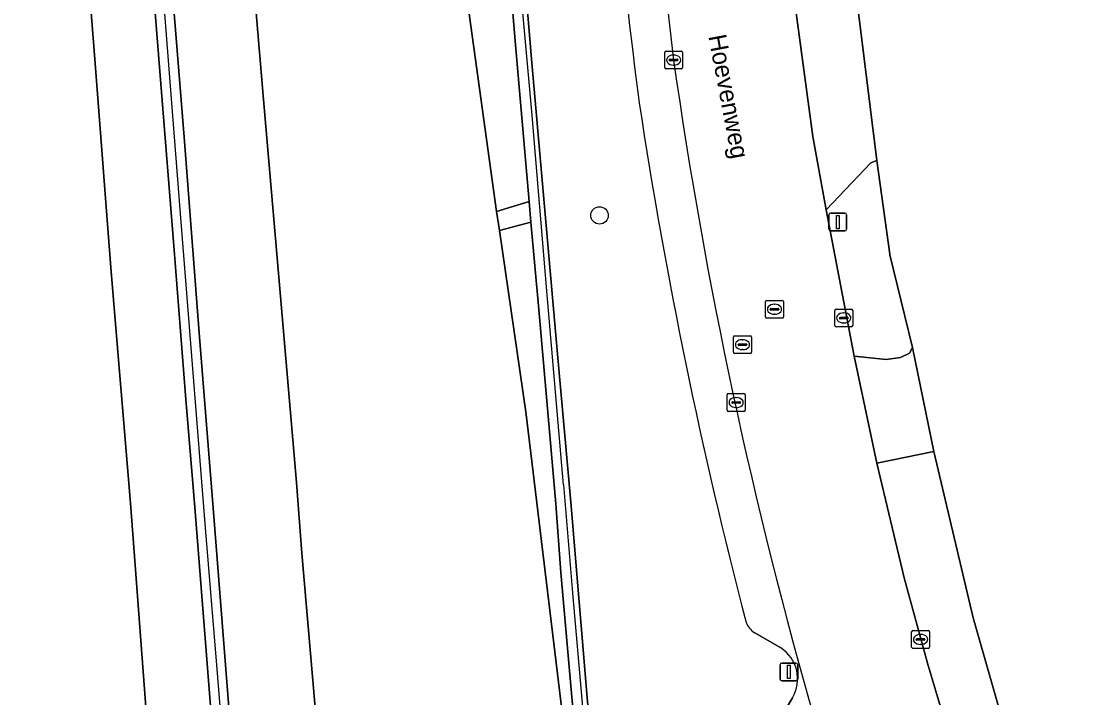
# Model space of a CAD drawing. Extents: x 157692 to 159674, y 381452 to 383291.
# Drawn here: x 157863.7 to 157922.9, y 381629.2 to 381667.1 of the extents above; entities that cross this region are included whole.
import ezdxf

# ---------------------------------------------------------------- set-up
doc = ezdxf.new("R2010")
doc.units = 0
for name, color, linetype in [('IMGEO_Berm_groen', 7, 'Continuous'), ('IMGEO_Boom', 7, 'Continuous'), ('IMGEO_Erf', 7, 'Continuous'), ('IMGEO_Geluidsscherm', 7, 'Continuous'), ('IMGEO_Groenvoorziening', 7, 'Continuous'), ('IMGEO_Kolk', 7, 'Continuous'), ('IMGEO_Lichtmast', 7, 'Continuous'), ('IMGEO_Muur', 7, 'Continuous'), ('IMGEO_Openbare_ruimte_label', 7, 'Continuous'), ('IMGEO_Parkeervlak_open', 7, 'Continuous'), ('IMGEO_Rijbaan_autosnelweg', 7, 'Continuous'), ('IMGEO_Rijbaan_autoweg', 7, 'Continuous'), ('IMGEO_Rijbaan_lokaal_gesloten', 7, 'Continuous'), ('IMGEO_Rioolput', 7, 'Continuous'), ('IMGEO_Voetpad_open', 7, 'Continuous')]:
    doc.layers.add(name, color=color, linetype=linetype)

msp = doc.modelspace()

# ---------------------------------------------------------------- linework, layer by layer
at = {"layer": 'IMGEO_Berm_groen'}
for points in [[(157867.965, 381722.303), (157868.994, 381709.276), (157869.88, 381698.16), (157870.87, 381685.864), (157871.828, 381673.372), (157872.842, 381660.625), (157873.712, 381649.4), (157874.498, 381639.59), (157875.594, 381625.546), (157876.484, 381614.198), (157877.279, 381604.704), (157878.126, 381593.661)], [(157877.434, 381589.695), (157876.669, 381599.29), (157875.872, 381609.289), (157874.963, 381620.654), (157874.164, 381630.852), (157873.473, 381639.621), (157872.935, 381646.148), (157872.278, 381654.539), (157871.543, 381663.616), (157870.896, 381671.836), (157870.352, 381678.919), (157869.739, 381686.472), (157869.25, 381692.912), (157868.64, 381700.422), (157867.915, 381709.715), (157867.171, 381719.374)], [(157863.732, 381717.086), (157864.635, 381706.057), (157865.474, 381695.412), (157866.333, 381684.381), (157867.087, 381674.55), (157867.859, 381664.764), (157868.754, 381653.066), (157869.845, 381640.086), (157870.805, 381627.181), (157871.895, 381613.885), (157872.944, 381600.363), (157873.76, 381590.175)], [(157884.249, 381713.789), (157885.718, 381694.582), (157886.683, 381684.924), (157887.404, 381678.445), (157888.701, 381668.639), (157890.369, 381656.458), (157892.204, 381657.014), (157892.013, 381659.154), (157891.404, 381666.233), (157890.517, 381676.962), (157889.471, 381689.083), (157888.65, 381698.565), (157887.932, 381707.729), (157887.155, 381717.191)], [(157883.242, 381593.296), (157882.445, 381602.817), (157881.422, 381614.915), (157880.419, 381626.031), (157879.461, 381637.285), (157879.148, 381641.247), (157878.255, 381651.695), (157877.308, 381662.744), (157876.45, 381672.935), (157875.49, 381684.241), (157874.611, 381694.819), (157873.682, 381705.524), (157873, 381713.591)]]:
    msp.add_lwpolyline(points, dxfattribs=at)
for points in [[(157890.369, 381656.458), (157890.552, 381655.387), (157892.308, 381655.853), (157892.204, 381657.014)], [(157896.492, 381572.256), (157899.256, 381574.148), (157898.47, 381584.121), (157897.751, 381592.572), (157897.07, 381600.846), (157896.254, 381610.059), (157895.493, 381618.788), (157894.791, 381627.105), (157893.991, 381636.202), (157893.71, 381640.067), (157892.745, 381650.96), (157892.308, 381655.853), (157890.552, 381655.387), (157892.024, 381645.22), (157894.258, 381626.649), (157895.097, 381617.5), (157896.096, 381606.158), (157896.433, 381601.439), (157896.643, 381597.697), (157896.668, 381594.368), (157896.501, 381586.539), (157896.379, 381579.545), (157896.402, 381576.024)]]:
    msp.add_lwpolyline(points, close=True, dxfattribs=at)
at = {"layer": 'IMGEO_Boom'}
msp.add_circle((157896.156, 381656.236), 0.489, dxfattribs=at)
at = {"layer": 'IMGEO_Erf'}
msp.add_lwpolyline([(157906.185, 381715.359), (157906.632, 381710.048), (157906.823, 381707.782), (157907.103, 381704.46), (157908.594, 381685.1), (157909.227, 381677.958), (157910.66, 381667.904), (157911.715, 381659.318), (157912.44, 381654.067), (157912.445, 381654.034), (157913.71, 381648.82), (157914.922, 381642.995), (157917.13, 381633.664), (157918.988, 381627.119), (157922.624, 381615.817), (157924.2, 381611.589)], dxfattribs=at)
at = {"layer": 'IMGEO_Geluidsscherm'}
for points in [[(157874.053, 381638.712), (157872.666, 381656.094), (157871.737, 381668.027), (157870.721, 381681.637), (157869.567, 381696.23), (157868.32, 381712.586), (157867.159, 381726.489), (157865.954, 381741.209), (157864.809, 381756.45), (157863.806, 381768.982), (157862.385, 381786.19), (157861.408, 381800.707), (157860.147, 381816.502), (157858.882, 381832.382), (157857.547, 381849.595), (157856.042, 381866.756), (157854.906, 381881.824), (157854.737, 381883.41), (157854.585, 381886.29)], [(157894.139, 381641.124), (157893.247, 381651.551), (157892.35, 381662.063), (157891.41, 381672.573), (157890.762, 381680.814), (157889.905, 381691.372), (157889.058, 381701.758), (157888.118, 381712.268), (157887.113, 381724.843), (157885.957, 381739.479), (157885.015, 381750.851), (157883.817, 381765.443), (157882.659, 381780.122), (157881.699, 381792.657), (157880.689, 381805.318), (157879.686, 381817.851), (157878.57, 381832.532), (157877.418, 381847.083), (157876.408, 381859.744), (157875.211, 381874.335), (157874.447, 381884.768)], [(157894.139, 381641.124), (157894.664, 381634.836), (157895.393, 381626.521), (157896.097, 381618.176), (157896.848, 381609.781), (157897.555, 381601.383), (157898.468, 381590.92), (157899.133, 381582.619)], [(157879.494, 381570.792), (157878.734, 381579.503), (157878.173, 381587.558), (157877.584, 381594.816), (157876.915, 381603.515), (157876.23, 381611.851), (157875.519, 381620.655), (157874.697, 381630.788), (157874.053, 381638.712)]]:
    msp.add_lwpolyline(points, dxfattribs=at)
at = {"layer": 'IMGEO_Groenvoorziening'}
for points in [[(157888.108, 381715.453), (157889.505, 381698.696), (157890.183, 381690.305), (157891.621, 381673.593), (157892.319, 381665.225), (157893.803, 381648.451), (157894.543, 381640.157), (157895.955, 381623.379), (157896.687, 381615.009), (157897.409, 381606.657), (157898.127, 381598.223)], [(157906.332, 381631.979), (157904.866, 381632.821)], [(157906.226, 381627.907), (157906.98, 381629.172)]]:
    msp.add_lwpolyline(points, dxfattribs=at)
for centre, radius, start, end in [((158259.967, 381709.911), 364.671, 183.80761, 187.46156), ((158179.201, 381705.152), 284.03, 188.62544, 194.63107), ((157905.554, 381633.882), 1.264, 201.99885, 237.01446), ((157905.189, 381630.237), 2.084, 329.27551, 56.72266)]:
    msp.add_arc(centre, radius, start, end, dxfattribs=at)
at = {"layer": 'IMGEO_Kolk'}
for p, q in [((157899.813, 381664.525), (157899.813, 381665.377)), ((157899.888, 381665.451), (157900.74, 381665.451)), ((157900.072, 381664.945), (157900.072, 381664.957)), ((157900.115, 381664.994), (157900.513, 381664.994)), ((157900.301, 381665.231), (157900.326, 381665.231)), ((157900.556, 381664.957), (157900.556, 381664.945)), ((157900.814, 381665.377), (157900.814, 381664.525)), ((157900.74, 381664.451), (157899.888, 381664.451)), ((157900.51, 381664.908), (157900.112, 381664.908)), ((157900.324, 381664.671), (157900.299, 381664.671)), ((157909.36, 381650.059), (157909.36, 381650.911)), ((157909.435, 381650.985), (157910.287, 381650.985)), ((157909.848, 381650.765), (157909.873, 381650.765)), ((157910.361, 381650.911), (157910.361, 381650.059)), ((157909.619, 381650.479), (157909.619, 381650.491)), ((157910.057, 381650.442), (157909.659, 381650.442)), ((157909.662, 381650.528), (157910.06, 381650.528)), ((157909.871, 381650.205), (157909.846, 381650.205)), ((157910.103, 381650.491), (157910.103, 381650.479)), ((157910.287, 381649.985), (157909.435, 381649.985)), ((157903.323, 381645.315), (157903.323, 381646.167)), ((157903.398, 381646.241), (157904.25, 381646.241)), ((157903.811, 381646.021), (157903.836, 381646.021)), ((157904.324, 381646.167), (157904.324, 381645.315)), ((157903.582, 381645.735), (157903.582, 381645.747)), ((157904.02, 381645.698), (157903.622, 381645.698)), ((157903.625, 381645.784), (157904.023, 381645.784)), ((157903.834, 381645.461), (157903.809, 381645.461)), ((157904.066, 381645.747), (157904.066, 381645.735)), ((157904.25, 381645.241), (157903.398, 381645.241)), ((157913.67, 381632.026), (157913.67, 381632.878)), ((157913.745, 381632.952), (157914.597, 381632.952)), ((157913.929, 381632.446), (157913.929, 381632.458)), ((157914.367, 381632.409), (157913.969, 381632.409)), ((157913.972, 381632.495), (157914.37, 381632.495)), ((157914.158, 381632.732), (157914.183, 381632.732)), ((157914.413, 381632.458), (157914.413, 381632.446)), ((157914.671, 381632.878), (157914.671, 381632.026)), ((157914.597, 381631.952), (157913.745, 381631.952)), ((157914.181, 381632.172), (157914.156, 381632.172))]:
    msp.add_line(p, q, dxfattribs=at)
for points in [[(157899.813, 381664.525), (157899.813, 381665.377)], [(157899.888, 381665.451), (157900.74, 381665.451)], [(157900.814, 381665.377), (157900.814, 381664.525)], [(157900.74, 381664.451), (157899.888, 381664.451)], [(157909.36, 381650.059), (157909.36, 381650.911)], [(157909.435, 381650.985), (157910.287, 381650.985)], [(157910.361, 381650.911), (157910.361, 381650.059)], [(157910.287, 381649.985), (157909.435, 381649.985)], [(157903.323, 381645.315), (157903.323, 381646.167)], [(157903.398, 381646.241), (157904.25, 381646.241)], [(157904.324, 381646.167), (157904.324, 381645.315)], [(157904.25, 381645.241), (157903.398, 381645.241)], [(157913.67, 381632.026), (157913.67, 381632.878)], [(157913.745, 381632.952), (157914.597, 381632.952)], [(157914.671, 381632.878), (157914.671, 381632.026)], [(157914.597, 381631.952), (157913.745, 381631.952)]]:
    msp.add_lwpolyline(points, dxfattribs=at)
for centre, radius, start, end in [((157899.89, 381665.375), 0.0765, 91.55205, 178.44795), ((157899.89, 381665.375), 0.0765, 91.55205, 178.44795), ((157900.112, 381664.954), 0.0403, 85.87752, 175.75265), ((157900.109, 381664.944), 0.0366, 178.93798, 274.71019), ((157900.513, 381664.951), 0.043, 264.86636, 352.45326), ((157900.517, 381664.956), 0.0386, 1.73085, 96.63898), ((157900.738, 381665.375), 0.0765, 1.55205, 88.44795), ((157900.738, 381665.375), 0.0765, 1.55205, 88.44795), ((157899.89, 381664.527), 0.0765, 181.55205, 268.44795), ((157899.89, 381664.527), 0.0765, 181.55205, 268.44795), ((157900.738, 381664.527), 0.0765, 271.55205, 358.44795), ((157900.738, 381664.527), 0.0765, 271.55205, 358.44795), ((157909.437, 381650.909), 0.0765, 91.55205, 178.44795), ((157909.437, 381650.909), 0.0765, 91.55205, 178.44795), ((157910.285, 381650.909), 0.0765, 1.55205, 88.44795), ((157910.285, 381650.909), 0.0765, 1.55205, 88.44795), ((157909.659, 381650.488), 0.0403, 85.87752, 175.75265), ((157909.656, 381650.478), 0.0366, 178.93798, 274.71019), ((157910.06, 381650.485), 0.043, 264.86636, 352.45326), ((157910.064, 381650.49), 0.0386, 1.73085, 96.63898), ((157909.437, 381650.061), 0.0765, 181.55205, 268.44795), ((157909.437, 381650.061), 0.0765, 181.55205, 268.44795), ((157910.285, 381650.061), 0.0765, 271.55205, 358.44795), ((157910.285, 381650.061), 0.0765, 271.55205, 358.44795), ((157903.4, 381646.165), 0.0765, 91.55205, 178.44795), ((157903.4, 381646.165), 0.0765, 91.55205, 178.44795), ((157904.248, 381646.165), 0.0765, 1.55205, 88.44795), ((157904.248, 381646.165), 0.0765, 1.55205, 88.44795), ((157903.622, 381645.744), 0.0403, 85.87752, 175.75265), ((157903.619, 381645.734), 0.0366, 178.93798, 274.71019), ((157904.023, 381645.741), 0.043, 264.86636, 352.45326), ((157904.027, 381645.746), 0.0386, 1.73085, 96.63898), ((157903.4, 381645.317), 0.0765, 181.55205, 268.44795), ((157903.4, 381645.317), 0.0765, 181.55205, 268.44795), ((157904.248, 381645.317), 0.0765, 271.55205, 358.44795), ((157904.248, 381645.317), 0.0765, 271.55205, 358.44795), ((157913.747, 381632.876), 0.0765, 91.55205, 178.44795), ((157913.747, 381632.876), 0.0765, 91.55205, 178.44795), ((157913.969, 381632.455), 0.0403, 85.87752, 175.75265), ((157913.966, 381632.445), 0.0366, 178.93798, 274.71019), ((157914.37, 381632.452), 0.043, 264.86636, 352.45326), ((157914.374, 381632.457), 0.0386, 1.73085, 96.63898), ((157914.595, 381632.876), 0.0765, 1.55205, 88.44795), ((157914.595, 381632.876), 0.0765, 1.55205, 88.44795), ((157913.747, 381632.028), 0.0765, 181.55205, 268.44795), ((157913.747, 381632.028), 0.0765, 181.55205, 268.44795), ((157914.595, 381632.028), 0.0765, 271.55205, 358.44795), ((157914.595, 381632.028), 0.0765, 271.55205, 358.44795)]:
    msp.add_arc(centre, radius, start, end, dxfattribs=at)
for centre, major_axis, ratio, start_param, end_param in [((157900.3, 381664.951), (-0.387, 0.002), 0.722429, 4.712389, 7.853982), ((157900.325, 381664.951), (-0.39, 0.002), 0.717154, 1.570796, 4.712389), ((157909.847, 381650.485), (-0.387, 0.002), 0.722429, 4.712389, 7.853982), ((157909.872, 381650.485), (-0.39, 0.002), 0.717154, 1.570796, 4.712389), ((157903.81, 381645.741), (-0.387, 0.002), 0.722429, 4.712389, 7.853982), ((157903.835, 381645.741), (-0.39, 0.002), 0.717154, 1.570796, 4.712389), ((157914.157, 381632.452), (-0.387, 0.002), 0.722429, 4.712389, 7.853982), ((157914.182, 381632.452), (-0.39, 0.002), 0.717154, 1.570796, 4.712389)]:
    msp.add_ellipse(centre, major_axis=major_axis, ratio=ratio, start_param=start_param, end_param=end_param, dxfattribs=at)
at = {"layer": 'IMGEO_Lichtmast'}
for p, q in [((157909.027, 381655.465), (157909.027, 381656.265)), ((157909.027, 381656.265), (157909.027, 381655.465)), ((157909.127, 381656.365), (157909.917, 381656.365)), ((157909.917, 381656.365), (157909.127, 381656.365)), ((157910.017, 381656.265), (157910.017, 381655.465)), ((157910.017, 381655.465), (157910.017, 381656.265)), ((157909.917, 381655.365), (157909.127, 381655.365)), ((157909.127, 381655.365), (157909.917, 381655.365)), ((157906.291, 381630.229), (157906.291, 381631.029)), ((157906.291, 381631.029), (157906.291, 381630.229)), ((157906.391, 381631.129), (157907.181, 381631.129)), ((157907.181, 381631.129), (157906.391, 381631.129)), ((157907.281, 381631.029), (157907.281, 381630.229)), ((157907.281, 381630.229), (157907.281, 381631.029)), ((157907.181, 381630.129), (157906.391, 381630.129)), ((157906.391, 381630.129), (157907.181, 381630.129))]:
    msp.add_line(p, q, dxfattribs=at)
for points in [[(157909.447, 381656.24), (157909.597, 381656.24), (157909.597, 381655.49), (157909.447, 381655.49), (157909.447, 381656.24)], [(157906.711, 381631.004), (157906.861, 381631.004), (157906.861, 381630.254), (157906.711, 381630.254), (157906.711, 381631.004)]]:
    msp.add_lwpolyline(points, dxfattribs=at)
for centre, start, end in [((157909.127, 381656.265), 90, 180), ((157909.127, 381656.265), 90, 180), ((157909.917, 381656.265), 0, 90), ((157909.917, 381656.265), 360, 90), ((157909.127, 381655.465), 180, 270), ((157909.127, 381655.465), 180, 270), ((157909.917, 381655.465), 270, 0), ((157909.917, 381655.465), 270, 0), ((157906.391, 381631.029), 90, 180), ((157906.391, 381631.029), 90, 180), ((157907.181, 381631.029), 0, 90), ((157907.181, 381631.029), 360, 90), ((157906.391, 381630.229), 180, 270), ((157906.391, 381630.229), 180, 270), ((157907.181, 381630.229), 270, 0), ((157907.181, 381630.229), 270, 0)]:
    msp.add_arc(centre, 0.1, start, end, dxfattribs=at)
at = {"layer": 'IMGEO_Muur'}
for points in [[(157878.126, 381593.661), (157877.279, 381604.704), (157876.484, 381614.198), (157875.594, 381625.546), (157874.498, 381639.59), (157873.712, 381649.4), (157872.842, 381660.625), (157871.828, 381673.372), (157870.87, 381685.864), (157869.88, 381698.16), (157868.994, 381709.276), (157867.965, 381722.303)], [(157867.171, 381719.374), (157867.915, 381709.715), (157868.64, 381700.422), (157869.25, 381692.912), (157869.739, 381686.472), (157870.352, 381678.919), (157870.896, 381671.836), (157871.543, 381663.616), (157872.278, 381654.539), (157872.935, 381646.148), (157873.473, 381639.621), (157874.164, 381630.852), (157874.963, 381620.654), (157875.872, 381609.289), (157876.669, 381599.29), (157877.434, 381589.695)], [(157887.155, 381717.191), (157887.932, 381707.729), (157888.65, 381698.565), (157889.471, 381689.083), (157890.517, 381676.962), (157891.404, 381666.233), (157892.013, 381659.154), (157892.204, 381657.014), (157892.308, 381655.853), (157892.745, 381650.96), (157893.71, 381640.067), (157893.991, 381636.202), (157894.791, 381627.105), (157895.493, 381618.788), (157896.254, 381610.059), (157897.07, 381600.846), (157897.751, 381592.572)], [(157898.127, 381598.223), (157897.409, 381606.657), (157896.687, 381615.009), (157895.955, 381623.379), (157894.543, 381640.157), (157893.803, 381648.451), (157892.319, 381665.225), (157891.621, 381673.593), (157890.183, 381690.305), (157889.505, 381698.696), (157888.108, 381715.453)]]:
    msp.add_lwpolyline(points, dxfattribs=at)
at = {"layer": 'IMGEO_Parkeervlak_open'}
for points in [[(157904.866, 381632.821), (157906.332, 381631.979)], [(157906.98, 381629.172), (157906.226, 381627.907)]]:
    msp.add_lwpolyline(points, dxfattribs=at)
for centre, radius, start, end in [((158259.967, 381709.911), 364.671, 183.80761, 187.46156), ((158256.833, 381709.082), 359.24, 183.68815, 187.05643), ((158168.422, 381702.972), 270.79, 188.07141, 196.11515), ((158179.201, 381705.152), 284.03, 188.62544, 194.63107), ((157905.554, 381633.882), 1.264, 201.99885, 237.01446), ((157905.189, 381630.237), 2.084, 329.27551, 56.72266)]:
    msp.add_arc(centre, radius, start, end, dxfattribs=at)
at = {"layer": 'IMGEO_Rijbaan_autosnelweg'}
msp.add_lwpolyline([(157873.76, 381590.175), (157872.944, 381600.363), (157871.895, 381613.885), (157870.805, 381627.181), (157869.845, 381640.086), (157868.754, 381653.066), (157867.859, 381664.764), (157867.087, 381674.55), (157866.333, 381684.381), (157865.474, 381695.412), (157864.635, 381706.057), (157863.732, 381717.086)], dxfattribs=at)
at = {"layer": 'IMGEO_Rijbaan_autoweg'}
for points in [[(157873, 381713.591), (157873.682, 381705.524), (157874.611, 381694.819), (157875.49, 381684.241), (157876.45, 381672.935), (157877.308, 381662.744), (157878.255, 381651.695), (157879.148, 381641.247), (157879.461, 381637.285), (157880.419, 381626.031), (157881.422, 381614.915), (157882.445, 381602.817), (157883.242, 381593.296)], [(157896.643, 381597.697), (157896.433, 381601.439), (157896.096, 381606.158), (157895.097, 381617.5), (157894.258, 381626.649), (157892.024, 381645.22), (157890.552, 381655.387), (157890.369, 381656.458), (157888.701, 381668.639), (157887.404, 381678.445), (157886.683, 381684.924), (157885.718, 381694.582), (157884.249, 381713.789)]]:
    msp.add_lwpolyline(points, dxfattribs=at)
at = {"layer": 'IMGEO_Rijbaan_lokaal_gesloten'}
for points in [[(157913.243, 381635.916), (157911.724, 381642.343), (157910.44, 381648.348), (157908.881, 381656.557), (157908.129, 381660.655), (157906.903, 381669.7), (157906.153, 381677.146), (157905.381, 381686.421), (157898.337, 381685.974)], [(158001.519, 381596.351), (158001.415, 381596.346), (157943.247, 381593.747), (157941.787, 381593.953), (157940.201, 381594.263), (157937.982, 381594.948), (157935.779, 381595.742), (157933.913, 381596.673), (157931.88, 381597.897), (157929.284, 381599.727), (157927.609, 381601.111), (157925.926, 381602.819), (157924.801, 381604.213), (157923.565, 381606.033), (157922.451, 381608.183), (157920.957, 381611.715), (157919.038, 381616.874), (157916.313, 381625.205), (157914.556, 381631.129), (157913.243, 381635.916)]]:
    msp.add_lwpolyline(points, dxfattribs=at)
for centre, radius, start, end in [((158256.833, 381709.082), 359.24, 183.68815, 187.05643), ((158168.422, 381702.972), 270.79, 188.07141, 196.11515)]:
    msp.add_arc(centre, radius, start, end, dxfattribs=at)
at = {"layer": 'IMGEO_Rioolput'}
for p, q in [((157905.475, 381650.546), (157905.475, 381651.398)), ((157905.55, 381651.472), (157906.402, 381651.472)), ((157906.476, 381651.398), (157906.476, 381650.546)), ((157905.734, 381650.966), (157905.734, 381650.978)), ((157906.172, 381650.929), (157905.774, 381650.929)), ((157905.777, 381651.015), (157906.175, 381651.015)), ((157905.963, 381651.252), (157905.988, 381651.252)), ((157906.218, 381650.978), (157906.218, 381650.966)), ((157906.402, 381650.472), (157905.55, 381650.472)), ((157905.986, 381650.692), (157905.961, 381650.692)), ((157903.679, 381648.56), (157903.679, 381649.412)), ((157903.754, 381649.486), (157904.606, 381649.486)), ((157903.938, 381648.98), (157903.938, 381648.992)), ((157904.376, 381648.943), (157903.978, 381648.943)), ((157903.981, 381649.029), (157904.379, 381649.029)), ((157904.167, 381649.266), (157904.192, 381649.266)), ((157904.422, 381648.992), (157904.422, 381648.98)), ((157904.68, 381649.412), (157904.68, 381648.56)), ((157904.606, 381648.486), (157903.754, 381648.486)), ((157904.19, 381648.706), (157904.165, 381648.706))]:
    msp.add_line(p, q, dxfattribs=at)
for points in [[(157905.475, 381650.546), (157905.475, 381651.398)], [(157905.55, 381651.472), (157906.402, 381651.472)], [(157906.476, 381651.398), (157906.476, 381650.546)], [(157906.402, 381650.472), (157905.55, 381650.472)], [(157903.679, 381648.56), (157903.679, 381649.412)], [(157903.754, 381649.486), (157904.606, 381649.486)], [(157904.68, 381649.412), (157904.68, 381648.56)], [(157904.606, 381648.486), (157903.754, 381648.486)]]:
    msp.add_lwpolyline(points, dxfattribs=at)
for centre, radius, start, end in [((157905.552, 381651.396), 0.0765, 91.55205, 178.44795), ((157905.552, 381651.396), 0.0765, 91.55205, 178.44795), ((157906.4, 381651.396), 0.0765, 1.55205, 88.44795), ((157906.4, 381651.396), 0.0765, 1.55205, 88.44795), ((157905.774, 381650.975), 0.0403, 85.87752, 175.75265), ((157905.771, 381650.965), 0.0366, 178.93798, 274.71019), ((157906.175, 381650.972), 0.043, 264.86636, 352.45326), ((157906.179, 381650.977), 0.0386, 1.73085, 96.63898), ((157905.552, 381650.548), 0.0765, 181.55205, 268.44795), ((157905.552, 381650.548), 0.0765, 181.55205, 268.44795), ((157906.4, 381650.548), 0.0765, 271.55205, 358.44795), ((157906.4, 381650.548), 0.0765, 271.55205, 358.44795), ((157903.756, 381649.41), 0.0765, 91.55205, 178.44795), ((157903.756, 381649.41), 0.0765, 91.55205, 178.44795), ((157903.978, 381648.989), 0.0403, 85.87752, 175.75265), ((157903.975, 381648.979), 0.0366, 178.93798, 274.71019), ((157904.379, 381648.986), 0.043, 264.86636, 352.45326), ((157904.383, 381648.991), 0.0386, 1.73085, 96.63898), ((157904.604, 381649.41), 0.0765, 1.55205, 88.44795), ((157904.604, 381649.41), 0.0765, 1.55205, 88.44795), ((157903.756, 381648.562), 0.0765, 181.55205, 268.44795), ((157903.756, 381648.562), 0.0765, 181.55205, 268.44795), ((157904.604, 381648.562), 0.0765, 271.55205, 358.44795), ((157904.604, 381648.562), 0.0765, 271.55205, 358.44795)]:
    msp.add_arc(centre, radius, start, end, dxfattribs=at)
for centre, major_axis, ratio, start_param, end_param in [((157905.962, 381650.972), (-0.387, 0.002), 0.722429, 4.712389, 7.853982), ((157905.987, 381650.972), (-0.39, 0.002), 0.717154, 1.570796, 4.712389), ((157904.166, 381648.986), (-0.387, 0.002), 0.722429, 4.712389, 7.853982), ((157904.191, 381648.986), (-0.39, 0.002), 0.717154, 1.570796, 4.712389)]:
    msp.add_ellipse(centre, major_axis=major_axis, ratio=ratio, start_param=start_param, end_param=end_param, dxfattribs=at)
at = {"layer": 'IMGEO_Voetpad_open'}
for points in [[(157908.881, 381656.557), (157911.376, 381659.193), (157911.715, 381659.318), (157910.66, 381667.904), (157909.798, 381667.902), (157906.903, 381669.7), (157908.129, 381660.655)], [(157911.715, 381659.318), (157911.376, 381659.193), (157908.881, 381656.557), (157910.44, 381648.348), (157912.236, 381648.161), (157913.049, 381648.268), (157913.554, 381648.51), (157913.71, 381648.82), (157912.445, 381654.034), (157912.44, 381654.067)], [(157914.922, 381642.995), (157913.71, 381648.82), (157913.554, 381648.51), (157913.049, 381648.268), (157912.236, 381648.161), (157910.44, 381648.348), (157911.724, 381642.343)]]:
    msp.add_lwpolyline(points, close=True, dxfattribs=at)
msp.add_lwpolyline([(157924.2, 381611.589), (157922.624, 381615.817), (157918.988, 381627.119), (157917.13, 381633.664), (157914.922, 381642.995), (157911.724, 381642.343), (157913.243, 381635.916), (157914.556, 381631.129), (157916.313, 381625.205), (157919.038, 381616.874), (157920.957, 381611.715), (157922.451, 381608.183), (157923.565, 381606.033)], dxfattribs=at)

# ---------------------------------------------------------------- texts
at = {"layer": 'IMGEO_Openbare_ruimte_label'}
msp.add_text('Hoevenweg', height=1, rotation=280.71464, dxfattribs=at).set_placement((157902.261, 381666.291))

doc.saveas('drawing.dxf')
